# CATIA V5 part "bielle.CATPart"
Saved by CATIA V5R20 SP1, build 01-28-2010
Part number: bielle1
Bounding box of the stored display mesh (mm): x 37.407 to 85.829, y -10 to 5, z 29.034 to 40.966
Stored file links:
  E:\EDELI\gcausse\Edeli_2012_681_gcausse\bielle.CATPart
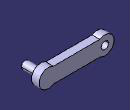
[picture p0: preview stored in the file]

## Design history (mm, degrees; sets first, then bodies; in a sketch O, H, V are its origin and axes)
Parameters
  long = 0.0367647
  diamtrou = 0.005
Body1 (main body)
  Sketch1 on zx-plane, origin (0, 0, 0), H (-1, 0, 0), V (0, 0, 1)
    line L1 (-46.5519, 40) -> (-76.6834, 40)
    line L2 (-46.5519, 30) -> (-76.6834, 30)
    arc A1 centre (-43.2353, 35) radius 6 from (-46.5519, 40) to (-46.5519, 30) cw
    point P5 (-43.2353, 35)
    point P6 (-39.9187, 30)
    arc A2 centre (-80, 35) radius 6 from (-76.6834, 40) to (-76.6834, 30) ccw
    point P7 (-80, 35)
    circle A3 centre (-43.2353, 35) radius 2.5
    distance P7 L1 = 5
    distance P5 L2 = 5
    distance L2 L1 = 10
    radius A1 = 6
    radius A2 = 6
    distance P5 P7 = 36.7647 {= long}
    radius A3 = 2.5
    horizontal: L1 H, L2 H
    coincidence: A1 P6, P6 L2
  Pad1: profile Sketch1, direction (0, 1, 0), length 5
  Sketch2 on start face of Pad1, origin (0, 0, 0), H (1, 0, 0), V (0, 0, 1)
    circle A1 centre (80, 35) radius 2.5
    reference projected arc E1 centre (80, 35) radius 6 from (75.8009, 30.7143) to (75.8009, 39.2857) ccw from edge [start face of Pad1 | face of Pad1 from Sketch1.A2]
    reference projected arc E2 centre (80, 35) radius 6 from (75.8009, 30.7143) to (75.8009, 39.2857) ccw from edge [start face of Pad1 | face of Pad1 from Sketch1.A2]
    radius A1 = 2.5
    radius E2 = 6 (reference)
    concentricity: A1 E1
  Pad2: profile Sketch2, direction (0, -1, 0), length 10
